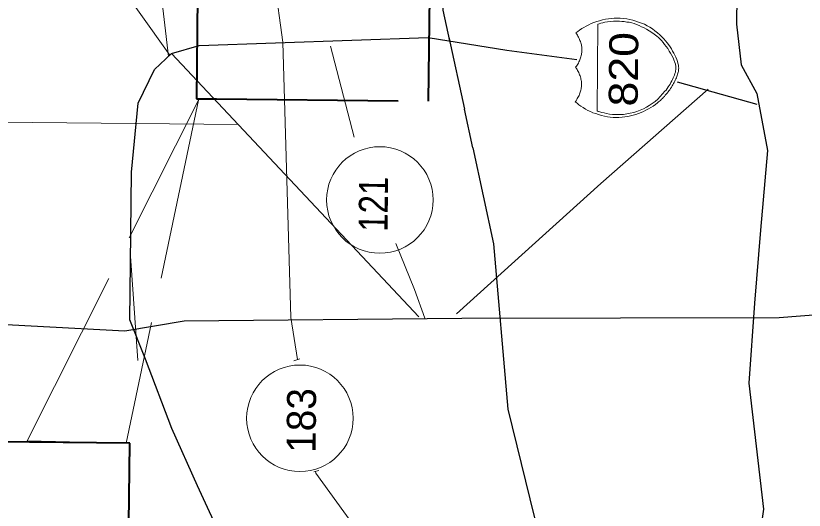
# Model space of a CAD drawing. Extents: x 2356576 to 2377878, y 6966390 to 6990634.
# Drawn here: x 2365828.3 to 2366013.1, y 6968885.6 to 6969001.5 of the extents above; entities that cross this region are included whole.
import ezdxf

# ---------------------------------------------------------------- set-up
doc = ezdxf.new("R2010")
doc.units = 0
doc.header["$LTSCALE"] = 7.1
doc.linetypes.add('LONG_DASHED', pattern=[7.5, 6, -1.5])
doc.layers.add('19', color=7, linetype='Continuous', lineweight=13)
doc.layers.add('8', color=7, linetype='Continuous', lineweight=13)

msp = doc.modelspace()

# ---------------------------------------------------------------- linework, layer by layer
at = {"layer": '19', "lineweight": 25}
for p, q in [((2365929.775, 6968996.506), (2365933.44, 6968979.635)), ((2365983.373, 6968986.018), (2366001.98, 6968980.757)), ((2365935.418, 6968970.522), (2365933.44, 6968979.635))]:
    msp.add_line(p, q, dxfattribs=at)
at = {"layer": '19'}
for p, q in [((2365907.631, 6968973.062), (2365902.091, 6968994.36)), ((2365864.807, 6968992.646), (2365922.763, 6968930.931)), ((2365880.416, 6968976.016), (2365821.947, 6968976.622)), ((2365921.722, 6968937.362), (2365917.361, 6968948.12)), ((2365856.921, 6968920.66), (2365855.167, 6968945.132)), ((2365921.722, 6968937.362), (2365924.2, 6968930.588)), ((2365893.495, 6968920.641), (2365894.852, 6968921.107)), ((2365898.177, 6968894.583), (2365899.32, 6968894.872)), ((2365898.538, 6968894.64), (2365898.594, 6968894.279))]:
    msp.add_line(p, q, dxfattribs=at)
at = {"layer": '19', "lineweight": 25}
for points in [[(2365993.212, 6969055.404), (2365995.144, 6969044.943), (2365996.174, 6969031.612), (2365997.392, 6969012.874), (2365997.254, 6968999.555), (2365998.323, 6968990.003), (2366002.006, 6968983.305), (2366004.476, 6968969.926), (2366002.874, 6968951.222), (2366001.496, 6968934.107), (2366000.162, 6968915.368), (2366003.604, 6968885.811), (2365999.567, 6968857.919), (2365994.142, 6968835.442), (2365986.716, 6968822.166), (2365969.062, 6968818.241), (2365951.423, 6968818.424), (2365942.698, 6968815.994), (2365930.315, 6968822.751)], [(2365928.079, 6969009.664), (2365928.4, 6969002.788), (2365929.974, 6968995.604)], [(2365864.807, 6968992.646), (2365871.279, 6968994.532), (2365924.942, 6968996.436)], [(2365924.942, 6968996.436), (2365943.364, 6968993.425), (2365959.814, 6968991.274)], [(2365891.759, 6968845.715), (2365883.197, 6968859.125), (2365877.06, 6968877.937), (2365870.87, 6968891.326), (2365864.889, 6968904.737), (2365858.697, 6968920.974), (2365855.04, 6968930.224), (2365855.178, 6968943.544), (2365855.399, 6968964.81), (2365856.978, 6968980.999), (2365860.808, 6968988.88), (2365864.807, 6968992.646)], [(2365935.418, 6968970.522), (2365940.314, 6968948.062), (2365943.664, 6968909.293), (2365950.886, 6968879.693), (2365951.331, 6968870.568)], [(2365867.731, 6968930.001), (2365932.844, 6968930.618), (2366007.222, 6968930.748), (2366102.256, 6968938.164), (2366144.393, 6968959.656)], [(2365793.72, 6968930.86), (2365853.846, 6968927.685), (2365867.731, 6968930.001)]]:
    msp.add_lwpolyline(points, dxfattribs=at)
at = {"layer": '19'}
for points in [[(2365864.052, 6968991.934), (2365861.157, 6969016.718), (2365858.758, 6969040.024)], [(2365840.889, 6969023.86), (2365850.012, 6969012.481), (2365864.416, 6968992.29)], [(2365886.944, 6969023.831), (2365890.88, 6968995.288), (2365892.792, 6968930.793), (2365894.338, 6968920.933)], [(2365960.165, 6968990.399), (2365960.288, 6968990.669), (2365960.411, 6968990.908), (2365960.501, 6968991.147), (2365960.624, 6968991.414), (2365960.686, 6968991.653), (2365960.781, 6968991.892), (2365960.844, 6968992.164), (2365960.874, 6968992.403), (2365960.937, 6968992.671), (2365960.999, 6968992.91), (2365961.002, 6968993.182), (2365961.005, 6968993.45), (2365961.007, 6968993.662), (2365961.01, 6968993.93), (2365960.953, 6968994.203), (2365960.895, 6968994.443), (2365960.87, 6968994.683), (2365960.812, 6968994.952), (2365960.723, 6968995.193), (2365960.665, 6968995.434), (2365960.548, 6968995.707), (2365960.463, 6968995.976), (2365960.345, 6968996.189), (2365960.228, 6968996.458), (2365960.079, 6968996.7), (2365959.961, 6968996.941), (2365959.784, 6968997.215), (2365959.607, 6968997.485), (2365960.03, 6968997.812), (2365960.453, 6968998.136), (2365960.969, 6968998.491), (2365961.48, 6968998.785), (2365962.023, 6968999.08), (2365962.599, 6968999.406), (2365963.201, 6968999.668), (2365963.804, 6968999.901), (2365964.494, 6969000.134), (2365965.156, 6969000.339), (2365965.819, 6969000.54), (2365966.512, 6969000.685), (2365967.201, 6969000.798), (2365967.894, 6969000.879), (2365968.555, 6969000.932), (2365969.275, 6969000.957), (2365969.995, 6969000.917), (2365970.774, 6969000.849), (2365971.521, 6969000.753), (2365972.212, 6969000.654), (2365972.931, 6969000.499), (2365973.648, 6969000.251), (2365974.306, 6969000.033), (2365974.991, 6968999.785), (2365975.648, 6968999.511), (2365976.305, 6968999.144), (2365976.901, 6968998.806), (2365977.529, 6968998.411), (2365978.124, 6968997.953), (2365978.692, 6968997.527), (2365979.255, 6968997.013), (2365979.789, 6968996.496), (2365980.177, 6968996.072), (2365980.593, 6968995.647), (2365980.976, 6968995.195), (2365981.331, 6968994.739), (2365981.658, 6968994.228), (2365981.981, 6968993.713), (2365982.276, 6968993.23), (2365982.57, 6968992.719), (2365982.806, 6968992.264), (2365983.041, 6968991.782), (2365983.248, 6968991.271), (2365983.423, 6968990.79), (2365983.506, 6968990.397), (2365983.622, 6968989.947), (2365983.678, 6968989.555), (2365983.706, 6968989.195)], [(2365983.706, 6968989.195), (2365983.672, 6968988.955), (2365983.669, 6968988.747), (2365983.639, 6968988.475), (2365983.576, 6968988.268), (2365983.514, 6968988.029), (2365983.451, 6968987.789), (2365983.357, 6968987.518), (2365983.266, 6968987.251), (2365983.143, 6968986.98), (2365983.048, 6968986.713), (2365982.897, 6968986.415), (2365982.775, 6968986.176), (2365982.652, 6968985.877), (2365982.497, 6968985.607), (2365982.314, 6968985.309), (2365982.163, 6968985.042), (2365981.98, 6968984.744), (2365981.797, 6968984.446), (2365981.582, 6968984.176), (2365981.399, 6968983.938), (2365981.217, 6968983.672), (2365980.974, 6968983.375), (2365980.763, 6968983.105), (2365980.549, 6968982.899), (2365980.338, 6968982.601), (2365980.123, 6968982.391), (2365979.881, 6968982.126), (2365979.67, 6968981.916), (2365979.428, 6968981.678), (2365979.214, 6968981.473), (2365978.972, 6968981.295), (2365978.73, 6968981.086), (2365978.218, 6968980.703), (2365977.674, 6968980.317), (2365977.126, 6968979.994), (2365976.583, 6968979.7), (2365976.012, 6968979.374), (2365975.437, 6968979.052), (2365974.866, 6968978.818), (2365974.232, 6968978.584), (2365973.661, 6968978.35), (2365972.999, 6968978.177), (2365972.366, 6968978.031), (2365971.736, 6968977.89), (2365971.075, 6968977.777), (2365970.414, 6968977.724), (2365969.694, 6968977.671), (2365969.034, 6968977.646), (2365968.314, 6968977.685), (2365967.655, 6968977.752), (2365966.964, 6968977.847), (2365966.277, 6968978.007), (2365965.586, 6968978.134), (2365964.929, 6968978.349), (2365964.271, 6968978.567), (2365963.585, 6968978.782), (2365962.988, 6968979.061), (2365962.391, 6968979.335), (2365961.822, 6968979.641), (2365961.285, 6968979.978), (2365960.781, 6968980.312), (2365960.272, 6968980.617), (2365959.856, 6968980.981), (2365959.439, 6968981.318), (2365959.622, 6968981.584), (2365959.805, 6968981.854), (2365959.927, 6968982.093), (2365960.082, 6968982.331), (2365960.204, 6968982.598), (2365960.327, 6968982.836), (2365960.418, 6968983.107), (2365960.54, 6968983.374), (2365960.603, 6968983.586), (2365960.697, 6968983.853), (2365960.76, 6968984.092), (2365960.791, 6968984.364), (2365960.854, 6968984.631), (2365960.916, 6968984.87), (2365960.918, 6968985.11), (2365960.921, 6968985.382), (2365960.924, 6968985.622), (2365960.927, 6968985.89), (2365960.869, 6968986.131), (2365960.812, 6968986.404), (2365960.786, 6968986.612), (2365960.729, 6968986.884), (2365960.64, 6968987.153), (2365960.582, 6968987.426), (2365960.465, 6968987.635), (2365960.379, 6968987.908), (2365960.262, 6968988.177), (2365960.145, 6968988.419), (2365959.995, 6968988.66), (2365959.878, 6968988.933), (2365959.7, 6968989.143), (2365959.523, 6968989.445), (2365959.706, 6968989.655), (2365959.888, 6968989.893), (2365960.011, 6968990.16), (2365960.165, 6968990.399)], [(2365990.583, 6968984.263), (2365965.421, 6968962.171), (2365931.591, 6968931.651)], [(2365898.594, 6968894.279), (2365917.316, 6968868.46), (2365940.231, 6968859.014)]]:
    msp.add_lwpolyline(points, dxfattribs=at)
at = {"layer": '19', "linetype": 'LONG_DASHED', "lineweight": 40}
msp.add_lwpolyline([(2365875.35, 6968982.009), (2365925.059, 6968981.494), (2365925.377, 6969012.18), (2365870.956, 6969012.744), (2365870.638, 6968982.057)], close=True, dxfattribs=at)
at = {"layer": '19'}
msp.add_lwpolyline([(2365964.76, 6968999.503), (2365964.549, 6968979.192), (2365964.848, 6968979.101), (2365965.235, 6968978.945), (2365965.654, 6968978.821), (2365966.193, 6968978.727), (2365966.791, 6968978.569), (2365967.481, 6968978.414), (2365968.201, 6968978.375), (2365969.041, 6968978.338), (2365969.849, 6968978.358), (2365970.721, 6968978.381), (2365971.531, 6968978.52), (2365972.344, 6968978.664), (2365973.154, 6968978.863), (2365973.877, 6968979.096), (2365974.692, 6968979.387), (2365975.415, 6968979.712), (2365976.107, 6968980.065), (2365976.803, 6968980.478), (2365977.5, 6968980.918), (2365978.165, 6968981.392), (2365978.771, 6968981.957), (2365979.377, 6968982.551), (2365979.923, 6968983.173), (2365980.47, 6968983.828), (2365980.741, 6968984.097), (2365980.957, 6968984.455), (2365981.228, 6968984.812), (2365981.444, 6968985.17), (2365981.656, 6968985.496), (2365981.871, 6968985.853), (2365982.055, 6968986.212), (2365982.239, 6968986.602), (2365982.39, 6968986.928), (2365982.546, 6968987.258), (2365982.698, 6968987.617), (2365982.821, 6968987.944), (2365982.916, 6968988.275), (2365982.98, 6968988.574), (2365983.011, 6968988.902), (2365983.046, 6968989.201), (2365982.99, 6968989.622), (2365982.936, 6968990.135), (2365982.76, 6968990.584), (2365982.586, 6968991.158), (2365982.379, 6968991.64), (2365982.085, 6968992.184), (2365981.791, 6968992.727), (2365981.496, 6968993.238), (2365981.142, 6968993.813), (2365980.759, 6968994.297), (2365980.404, 6968994.781), (2365980.017, 6968995.265), (2365979.661, 6968995.717), (2365979.305, 6968996.081), (2365978.921, 6968996.445), (2365978.592, 6968996.72), (2365977.968, 6968997.174), (2365977.369, 6968997.601), (2365976.773, 6968997.967), (2365976.148, 6968998.333), (2365975.58, 6968998.671), (2365974.983, 6968998.945), (2365974.417, 6968999.223), (2365973.82, 6968999.438), (2365973.222, 6968999.656), (2365972.683, 6968999.809), (2365972.085, 6968999.968), (2365971.514, 6969000.033), (2365970.947, 6969000.127), (2365970.375, 6969000.193), (2365969.808, 6969000.231), (2365969.268, 6969000.265), (2365968.428, 6969000.245), (2365967.707, 6969000.193), (2365967.014, 6969000.08), (2365966.413, 6969000.026), (2365965.872, 6968999.88), (2365965.45, 6968999.736), (2365965.061, 6968999.62)], close=True, dxfattribs=at)
at = {"layer": '19', "linetype": 'LONG_DASHED'}
for points in [[(2365830.925, 6968901.881), (2365871.114, 6968981.693), (2365854.172, 6968901.28)], [(2365830.925, 6968901.881), (2365871.114, 6968981.693), (2365854.172, 6968901.28), (2365830.925, 6968901.881)]]:
    msp.add_lwpolyline(points, close=True, dxfattribs=at)
at = {"layer": '19', "linetype": 'LONG_DASHED', "lineweight": 40}
msp.add_lwpolyline([(2365767.5, 6968670.405), (2365852.579, 6968669.524), (2365854.981, 6968901.299), (2365769.901, 6968902.181), (2365767.496, 6968669.985)], dxfattribs=at)
at = {"layer": '19'}
for centre in [(2365913.633, 6968958.331), (2365894.888, 6968907.144)]:
    msp.add_circle(centre, 12.486, dxfattribs=at)
at = {"layer": '8', "lineweight": 25}
for p, q in [((2365929.775, 6968996.506), (2365933.44, 6968979.635)), ((2365983.373, 6968986.018), (2366001.98, 6968980.757)), ((2365935.418, 6968970.522), (2365933.44, 6968979.635))]:
    msp.add_line(p, q, dxfattribs=at)
at = {"layer": '8'}
for p, q in [((2365907.631, 6968973.062), (2365902.091, 6968994.36)), ((2365864.807, 6968992.646), (2365922.763, 6968930.931)), ((2365880.416, 6968976.016), (2365821.947, 6968976.622)), ((2365921.722, 6968937.362), (2365917.361, 6968948.12)), ((2365856.921, 6968920.66), (2365855.167, 6968945.132)), ((2365921.722, 6968937.362), (2365924.2, 6968930.588)), ((2365893.495, 6968920.641), (2365894.852, 6968921.107)), ((2365898.177, 6968894.583), (2365899.32, 6968894.872)), ((2365898.538, 6968894.64), (2365898.594, 6968894.279))]:
    msp.add_line(p, q, dxfattribs=at)
at = {"layer": '8', "lineweight": 25}
for points in [[(2365993.212, 6969055.404), (2365995.144, 6969044.943), (2365996.174, 6969031.612), (2365997.392, 6969012.874), (2365997.254, 6968999.555), (2365998.323, 6968990.003), (2366002.006, 6968983.305), (2366004.476, 6968969.926), (2366002.874, 6968951.222), (2366001.496, 6968934.107), (2366000.162, 6968915.368), (2366003.604, 6968885.811), (2365999.567, 6968857.919), (2365994.142, 6968835.442), (2365986.716, 6968822.166), (2365969.062, 6968818.241), (2365951.423, 6968818.424), (2365942.698, 6968815.994), (2365930.315, 6968822.751)], [(2365928.079, 6969009.664), (2365928.4, 6969002.788), (2365929.974, 6968995.604)], [(2365864.807, 6968992.646), (2365871.279, 6968994.532), (2365924.942, 6968996.436)], [(2365924.942, 6968996.436), (2365943.364, 6968993.425), (2365959.814, 6968991.274)], [(2365891.759, 6968845.715), (2365883.197, 6968859.125), (2365877.06, 6968877.937), (2365870.87, 6968891.326), (2365864.889, 6968904.737), (2365858.697, 6968920.974), (2365855.04, 6968930.224), (2365855.178, 6968943.544), (2365855.399, 6968964.81), (2365856.978, 6968980.999), (2365860.808, 6968988.88), (2365864.807, 6968992.646)], [(2365935.418, 6968970.522), (2365940.314, 6968948.062), (2365943.664, 6968909.293), (2365950.886, 6968879.693), (2365951.331, 6968870.568)], [(2365867.731, 6968930.001), (2365932.844, 6968930.618), (2366007.222, 6968930.748), (2366102.256, 6968938.164), (2366144.393, 6968959.656)], [(2365793.72, 6968930.86), (2365853.846, 6968927.685), (2365867.731, 6968930.001)]]:
    msp.add_lwpolyline(points, dxfattribs=at)
at = {"layer": '8'}
for points in [[(2365864.052, 6968991.934), (2365861.157, 6969016.718), (2365858.758, 6969040.024)], [(2365840.889, 6969023.86), (2365850.012, 6969012.481), (2365864.416, 6968992.29)], [(2365886.944, 6969023.831), (2365890.88, 6968995.288), (2365892.792, 6968930.793), (2365894.338, 6968920.933)], [(2365960.165, 6968990.399), (2365960.288, 6968990.669), (2365960.411, 6968990.908), (2365960.501, 6968991.147), (2365960.624, 6968991.414), (2365960.686, 6968991.653), (2365960.781, 6968991.892), (2365960.844, 6968992.164), (2365960.874, 6968992.403), (2365960.937, 6968992.671), (2365960.999, 6968992.91), (2365961.002, 6968993.182), (2365961.005, 6968993.45), (2365961.007, 6968993.662), (2365961.01, 6968993.93), (2365960.953, 6968994.203), (2365960.895, 6968994.443), (2365960.87, 6968994.683), (2365960.812, 6968994.952), (2365960.723, 6968995.193), (2365960.665, 6968995.434), (2365960.548, 6968995.707), (2365960.463, 6968995.976), (2365960.345, 6968996.189), (2365960.228, 6968996.458), (2365960.079, 6968996.7), (2365959.961, 6968996.941), (2365959.784, 6968997.215), (2365959.607, 6968997.485), (2365960.03, 6968997.812), (2365960.453, 6968998.136), (2365960.969, 6968998.491), (2365961.48, 6968998.785), (2365962.023, 6968999.08), (2365962.599, 6968999.406), (2365963.201, 6968999.668), (2365963.804, 6968999.901), (2365964.494, 6969000.134), (2365965.156, 6969000.339), (2365965.819, 6969000.54), (2365966.512, 6969000.685), (2365967.201, 6969000.798), (2365967.894, 6969000.879), (2365968.555, 6969000.932), (2365969.275, 6969000.957), (2365969.995, 6969000.917), (2365970.774, 6969000.849), (2365971.521, 6969000.753), (2365972.212, 6969000.654), (2365972.931, 6969000.499), (2365973.648, 6969000.251), (2365974.306, 6969000.033), (2365974.991, 6968999.785), (2365975.648, 6968999.511), (2365976.305, 6968999.144), (2365976.901, 6968998.806), (2365977.529, 6968998.411), (2365978.124, 6968997.953), (2365978.692, 6968997.527), (2365979.255, 6968997.013), (2365979.789, 6968996.496), (2365980.177, 6968996.072), (2365980.593, 6968995.647), (2365980.976, 6968995.195), (2365981.331, 6968994.739), (2365981.658, 6968994.228), (2365981.981, 6968993.713), (2365982.276, 6968993.23), (2365982.57, 6968992.719), (2365982.806, 6968992.264), (2365983.041, 6968991.782), (2365983.248, 6968991.271), (2365983.423, 6968990.79), (2365983.506, 6968990.397), (2365983.622, 6968989.947), (2365983.678, 6968989.555), (2365983.706, 6968989.195)], [(2365983.706, 6968989.195), (2365983.672, 6968988.955), (2365983.669, 6968988.747), (2365983.639, 6968988.475), (2365983.576, 6968988.268), (2365983.514, 6968988.029), (2365983.451, 6968987.789), (2365983.357, 6968987.518), (2365983.266, 6968987.251), (2365983.143, 6968986.98), (2365983.048, 6968986.713), (2365982.897, 6968986.415), (2365982.775, 6968986.176), (2365982.652, 6968985.877), (2365982.497, 6968985.607), (2365982.314, 6968985.309), (2365982.163, 6968985.042), (2365981.98, 6968984.744), (2365981.797, 6968984.446), (2365981.582, 6968984.176), (2365981.399, 6968983.938), (2365981.217, 6968983.672), (2365980.974, 6968983.375), (2365980.763, 6968983.105), (2365980.549, 6968982.899), (2365980.338, 6968982.601), (2365980.123, 6968982.391), (2365979.881, 6968982.126), (2365979.67, 6968981.916), (2365979.428, 6968981.678), (2365979.214, 6968981.473), (2365978.972, 6968981.295), (2365978.73, 6968981.086), (2365978.218, 6968980.703), (2365977.674, 6968980.317), (2365977.126, 6968979.994), (2365976.583, 6968979.7), (2365976.012, 6968979.374), (2365975.437, 6968979.052), (2365974.866, 6968978.818), (2365974.232, 6968978.584), (2365973.661, 6968978.35), (2365972.999, 6968978.177), (2365972.366, 6968978.031), (2365971.736, 6968977.89), (2365971.075, 6968977.777), (2365970.414, 6968977.724), (2365969.694, 6968977.671), (2365969.034, 6968977.646), (2365968.314, 6968977.685), (2365967.655, 6968977.752), (2365966.964, 6968977.847), (2365966.277, 6968978.007), (2365965.586, 6968978.134), (2365964.929, 6968978.349), (2365964.271, 6968978.567), (2365963.585, 6968978.782), (2365962.988, 6968979.061), (2365962.391, 6968979.335), (2365961.822, 6968979.641), (2365961.285, 6968979.978), (2365960.781, 6968980.312), (2365960.272, 6968980.617), (2365959.856, 6968980.981), (2365959.439, 6968981.318), (2365959.622, 6968981.584), (2365959.805, 6968981.854), (2365959.927, 6968982.093), (2365960.082, 6968982.331), (2365960.204, 6968982.598), (2365960.327, 6968982.836), (2365960.418, 6968983.107), (2365960.54, 6968983.374), (2365960.603, 6968983.586), (2365960.697, 6968983.853), (2365960.76, 6968984.092), (2365960.791, 6968984.364), (2365960.854, 6968984.631), (2365960.916, 6968984.87), (2365960.918, 6968985.11), (2365960.921, 6968985.382), (2365960.924, 6968985.622), (2365960.927, 6968985.89), (2365960.869, 6968986.131), (2365960.812, 6968986.404), (2365960.786, 6968986.612), (2365960.729, 6968986.884), (2365960.64, 6968987.153), (2365960.582, 6968987.426), (2365960.465, 6968987.635), (2365960.379, 6968987.908), (2365960.262, 6968988.177), (2365960.145, 6968988.419), (2365959.995, 6968988.66), (2365959.878, 6968988.933), (2365959.7, 6968989.143), (2365959.523, 6968989.445), (2365959.706, 6968989.655), (2365959.888, 6968989.893), (2365960.011, 6968990.16), (2365960.165, 6968990.399)], [(2365990.583, 6968984.263), (2365965.421, 6968962.171), (2365931.591, 6968931.651)], [(2365898.594, 6968894.279), (2365917.316, 6968868.46), (2365940.231, 6968859.014)]]:
    msp.add_lwpolyline(points, dxfattribs=at)
at = {"layer": '8', "linetype": 'LONG_DASHED', "lineweight": 40}
msp.add_lwpolyline([(2365875.35, 6968982.009), (2365925.059, 6968981.494), (2365925.377, 6969012.18), (2365870.956, 6969012.744), (2365870.638, 6968982.057)], close=True, dxfattribs=at)
at = {"layer": '8'}
msp.add_lwpolyline([(2365964.76, 6968999.503), (2365964.549, 6968979.192), (2365964.848, 6968979.101), (2365965.235, 6968978.945), (2365965.654, 6968978.821), (2365966.193, 6968978.727), (2365966.791, 6968978.569), (2365967.481, 6968978.414), (2365968.201, 6968978.375), (2365969.041, 6968978.338), (2365969.849, 6968978.358), (2365970.721, 6968978.381), (2365971.531, 6968978.52), (2365972.344, 6968978.664), (2365973.154, 6968978.863), (2365973.877, 6968979.096), (2365974.692, 6968979.387), (2365975.415, 6968979.712), (2365976.107, 6968980.065), (2365976.803, 6968980.478), (2365977.5, 6968980.918), (2365978.165, 6968981.392), (2365978.771, 6968981.957), (2365979.377, 6968982.551), (2365979.923, 6968983.173), (2365980.47, 6968983.828), (2365980.741, 6968984.097), (2365980.957, 6968984.455), (2365981.228, 6968984.812), (2365981.444, 6968985.17), (2365981.656, 6968985.496), (2365981.871, 6968985.853), (2365982.055, 6968986.212), (2365982.239, 6968986.602), (2365982.39, 6968986.928), (2365982.546, 6968987.258), (2365982.698, 6968987.617), (2365982.821, 6968987.944), (2365982.916, 6968988.275), (2365982.98, 6968988.574), (2365983.011, 6968988.902), (2365983.046, 6968989.201), (2365982.99, 6968989.622), (2365982.936, 6968990.135), (2365982.76, 6968990.584), (2365982.586, 6968991.158), (2365982.379, 6968991.64), (2365982.085, 6968992.184), (2365981.791, 6968992.727), (2365981.496, 6968993.238), (2365981.142, 6968993.813), (2365980.759, 6968994.297), (2365980.404, 6968994.781), (2365980.017, 6968995.265), (2365979.661, 6968995.717), (2365979.305, 6968996.081), (2365978.921, 6968996.445), (2365978.592, 6968996.72), (2365977.968, 6968997.174), (2365977.369, 6968997.601), (2365976.773, 6968997.967), (2365976.148, 6968998.333), (2365975.58, 6968998.671), (2365974.983, 6968998.945), (2365974.417, 6968999.223), (2365973.82, 6968999.438), (2365973.222, 6968999.656), (2365972.683, 6968999.809), (2365972.085, 6968999.968), (2365971.514, 6969000.033), (2365970.947, 6969000.127), (2365970.375, 6969000.193), (2365969.808, 6969000.231), (2365969.268, 6969000.265), (2365968.428, 6969000.245), (2365967.707, 6969000.193), (2365967.014, 6969000.08), (2365966.413, 6969000.026), (2365965.872, 6968999.88), (2365965.45, 6968999.736), (2365965.061, 6968999.62)], close=True, dxfattribs=at)
at = {"layer": '8', "linetype": 'LONG_DASHED'}
for points in [[(2365830.925, 6968901.881), (2365871.114, 6968981.693), (2365854.172, 6968901.28)], [(2365830.925, 6968901.881), (2365871.114, 6968981.693), (2365854.172, 6968901.28), (2365830.925, 6968901.881)]]:
    msp.add_lwpolyline(points, close=True, dxfattribs=at)
at = {"layer": '8', "linetype": 'LONG_DASHED', "lineweight": 40}
msp.add_lwpolyline([(2365767.5, 6968670.405), (2365852.579, 6968669.524), (2365854.981, 6968901.299), (2365769.901, 6968902.181), (2365767.496, 6968669.985)], dxfattribs=at)
at = {"layer": '8'}
for centre in [(2365913.633, 6968958.331), (2365894.888, 6968907.144)]:
    msp.add_circle(centre, 12.486, dxfattribs=at)

# ---------------------------------------------------------------- texts
at = {"layer": '19'}
for s, width, p in [('820', 1.15, (2365974.068, 6968980.206)), ('121', 0.85, (2365915.441, 6968950.84))]:
    msp.add_text(s, height=6.798, rotation=89.406, dxfattribs=dict(at, width=width)).set_placement(p)
msp.add_text('183', height=6.798, rotation=89.406, dxfattribs=at).set_placement((2365898.551, 6968899.02))
at = {"layer": '8'}
for s, width, p in [('820', 1.15, (2365974.068, 6968980.206)), ('121', 0.85, (2365915.441, 6968950.84))]:
    msp.add_text(s, height=6.798, rotation=89.406, dxfattribs=dict(at, width=width)).set_placement(p)
msp.add_text('183', height=6.798, rotation=89.406, dxfattribs=at).set_placement((2365898.551, 6968899.02))

doc.saveas('drawing.dxf')
